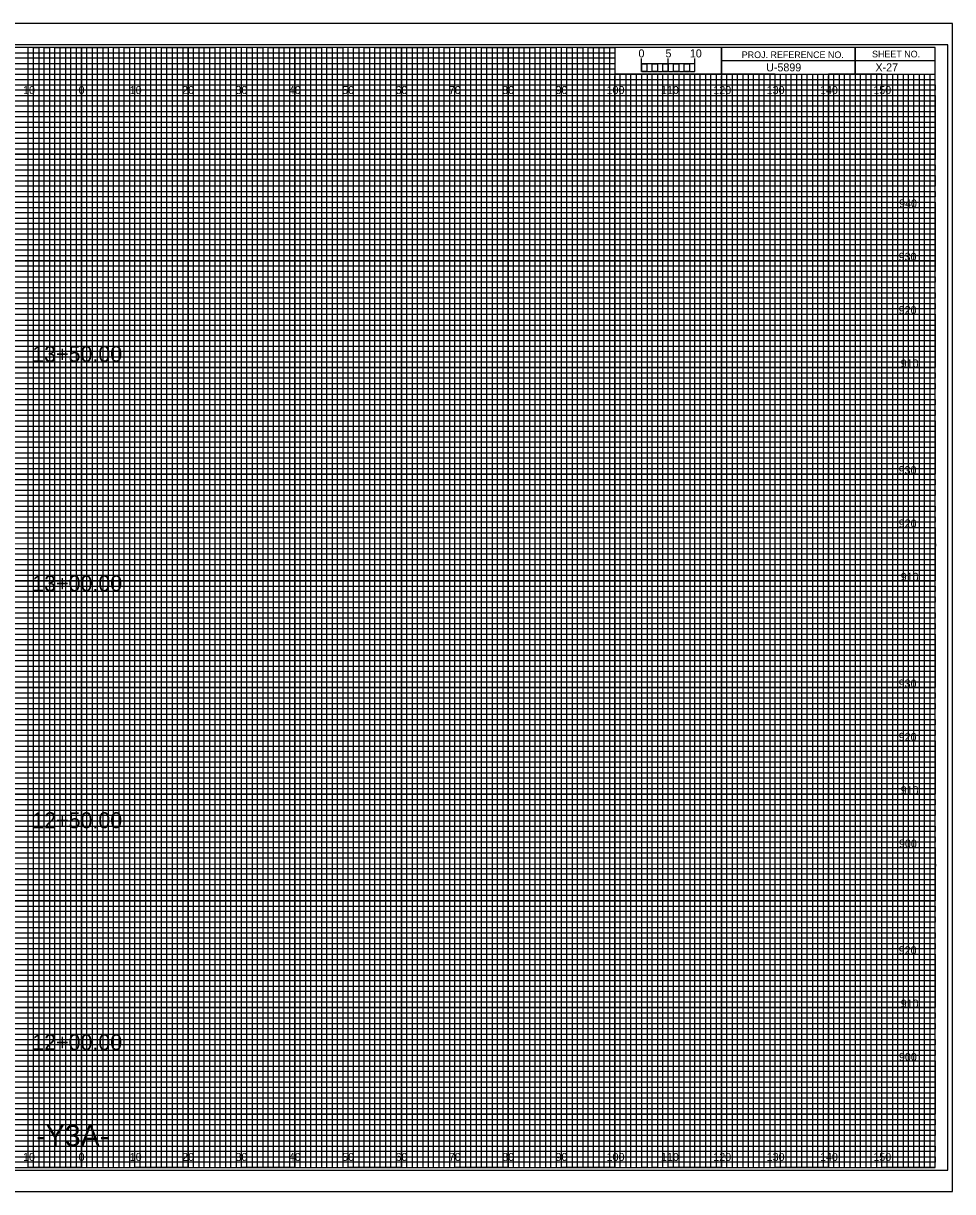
# Model space of a CAD drawing. Extents: x -13 to 323, y 216 to 434.
# Drawn here: x 149.1 to 323.3, y 215.5 to 434.5 of the extents above; entities that cross this region are included whole.
import ezdxf

# ---------------------------------------------------------------- set-up
doc = ezdxf.new("R2010")
doc.units = 0
for name, color, linetype in [('Prop XS Alignment Label', 7, 'Continuous'), ('Prop XS Bar Scale Labels', 7, 'Continuous'), ('Prop XS Elevation Labels', 7, 'Continuous'), ('Prop XS Label Text', 7, 'Continuous'), ('Prop XS Project Number', 7, 'Continuous'), ('Prop XS Sheet Number', 7, 'Continuous'), ('Prop XS Station Labels', 7, 'Continuous'), ('Scratch_Level_1', 7, 'Continuous'), ('Scratch_Level_4', 7, 'Continuous'), ('Sheet Cross Section CELL', 7, 'Continuous'), ('Sheet Cross Section Grid Minor 1 CELL', 7, 'Continuous'), ('Sheet Cross Section Grid Minor 2 CELL', 7, 'Continuous'), ('Sheet Cross Section Scale CELL', 7, 'Continuous'), ('Sheet Cutting Line CELL', 7, 'Continuous'), ('Sheet DOT Grid CELL', 7, 'Continuous'), ('Sheet Plot Border Inside CELL', 7, 'Continuous'), ('Sheet Plot Border Outside CELL', 7, 'Continuous')]:
    doc.layers.add(name, color=color, linetype=linetype)

msp = doc.modelspace()

# ---------------------------------------------------------------- linework, layer by layer
at = {"layer": 'Prop XS Label Text'}
for points in [[(145, 220), (155, 220), (155, 430), (165, 430), (165, 220), (175, 220), (175, 430), (185, 430), (185, 220), (195, 220), (195, 430), (205, 430), (205, 220), (215, 220), (215, 430), (225, 430), (225, 220), (235, 220), (235, 430), (245, 430), (245, 220), (255, 220), (255, 430), (259.93, 430), (260, 430), (260, 425), (264.99, 425), (264.99, 220), (275, 220), (275, 425), (285, 425), (285, 220), (295, 220), (295, 425), (305, 425), (305, 220), (315, 220), (315, 425)], [(0, 425), (275, 425)], [(0, 405), (320, 405), (320, 415), (0, 415)], [(0, 385), (320, 385), (320, 395), (0, 395)], [(0, 365), (320, 365), (320, 375), (0, 375)], [(0, 345), (320, 345), (320, 355), (0, 355)], [(0, 325), (320, 325), (320, 335), (0, 335)], [(0, 305), (320, 305), (320, 315), (0, 315)], [(0, 285), (320, 285), (320, 295), (0, 295)], [(0, 265), (320, 265), (320, 275), (0, 275)], [(0, 245), (320, 245), (320, 255), (0, 255)], [(0, 225), (320, 225), (320, 235), (0, 235)]]:
    msp.add_lwpolyline(points, dxfattribs=at)
at = {"layer": 'Scratch_Level_4'}
for p, q in [((150, 430), (140, 430)), ((150, 220), (150, 430)), ((170, 430), (160, 430)), ((160, 430), (160, 220)), ((170, 220), (170, 430)), ((190, 430), (180, 430)), ((180, 430), (180, 220)), ((190, 220), (190, 430)), ((210, 430), (200, 430)), ((200, 430), (200, 220)), ((210, 220), (210, 430)), ((230, 430), (220, 430)), ((220, 430), (220, 220)), ((230, 220), (230, 430)), ((250, 430), (240, 430)), ((240, 430), (240, 220)), ((250, 220), (250, 430)), ((260, 430), (260, 220)), ((270, 220), (270, 425)), ((290, 425), (280, 425)), ((280, 425), (280, 220)), ((290, 220), (290, 425)), ((310, 425), (300, 425)), ((300, 425), (300, 220)), ((310, 220), (310, 425)), ((160, 220), (150, 220)), ((180, 220), (170, 220)), ((200, 220), (190, 220)), ((220, 220), (210, 220)), ((240, 220), (230, 220)), ((260, 220), (250, 220)), ((280, 220), (270, 220)), ((300, 220), (290, 220)), ((320, 220), (310, 220)), ((320, 220), (320, 220))]:
    msp.add_line(p, q, dxfattribs=at)
for points in [[(0, 420), (320, 420), (320, 410), (0, 410)], [(0, 400), (320, 400), (320, 390), (0, 390)], [(0, 380), (320, 380), (320, 370), (0, 370)], [(0, 360), (320, 360), (320, 350), (0, 350)], [(0, 340), (320, 340), (320, 330), (0, 330)], [(0, 320), (320, 320), (320, 310), (0, 310)], [(0, 300), (320, 300), (320, 290), (0, 290)], [(0, 280), (320, 280), (320, 270), (0, 270)], [(0, 260), (320, 260), (320, 250), (0, 250)], [(0, 240), (320, 240), (320, 230), (0, 230)]]:
    msp.add_lwpolyline(points, dxfattribs=at)
at = {"layer": 'Sheet Cross Section CELL'}
for p, q in [((305, 430), (305, 425)), ((305, 425), (305, 430)), ((280, 427.5), (280, 425)), ((320, 427.49), (280, 427.49)), ((280, 425), (320, 425))]:
    msp.add_line(p, q, dxfattribs=at)
for points in [[(320, 430), (0, 430), (0, 220), (320, 220)], [(280, 430), (260, 430), (260, 425.03), (280, 425.03)], [(320, 430), (280, 430), (280, 425), (320, 425)]]:
    msp.add_lwpolyline(points, close=True, dxfattribs=at)
at = {"layer": 'Sheet Cross Section Grid Minor 1 CELL'}
for p, q in [((0, 429), (260, 429)), ((260, 427.98), (0, 427.98)), ((260, 429), (260, 427.98)), ((0, 427), (260, 427)), ((260, 425.89), (0, 425.89)), ((260, 427), (260, 425.89)), ((0, 424), (320, 424))]:
    msp.add_line(p, q, dxfattribs=at)
for points in [[(0, 423), (270, 423), (320, 423), (320, 422), (0, 422)], [(0, 421), (320, 421), (320, 419), (0, 419)], [(0, 418), (320, 418), (320, 417), (0, 416.98)], [(0, 416), (320, 416), (320, 414), (0, 414)], [(0, 413), (320, 413), (320, 412), (0, 412)], [(0, 411), (320, 411), (320, 409), (0, 409)], [(0, 408), (320, 408), (320, 407), (0, 407)], [(0, 406), (320, 406), (320, 404), (0, 404)], [(0, 403), (320, 403), (320, 402), (0, 402)], [(0, 401), (320, 401), (320, 399), (0, 399)], [(0, 398), (320, 398), (320, 397), (0, 397)], [(0, 396), (320, 396), (320, 393.95), (320, 393), (320, 392), (0, 392)], [(0, 394), (320, 394), (320, 393), (0, 393)], [(0, 391), (320, 391), (320, 389), (0, 389.03)], [(0, 389.03), (320, 389), (320, 388), (0, 388)], [(0, 387), (320, 387), (320, 386), (0, 386)], [(0, 384), (320, 384), (320, 383), (0, 383)], [(0, 382), (320, 382), (320, 381), (0, 381)], [(-0.07, 378.89), (320, 378.89), (320, 377.88), (-0.07, 377.88)], [(0, 377), (320, 377), (320, 376), (0, 376)], [(0, 374), (320, 374), (320, 373), (0, 373)], [(0, 372), (320, 372), (320, 371), (0, 371)], [(0, 369), (320, 369), (320, 368), (0, 368)], [(0, 367), (320, 367), (320, 366), (0, 366)], [(0, 364), (320, 364), (320, 363), (0, 363)], [(0, 362), (320, 362), (320, 361), (0, 361)], [(0, 359), (320, 359), (319.99, 357.98), (0, 358)], [(0, 357), (320, 357), (320, 356), (0, 356)], [(0, 354), (320, 354), (320, 353), (0, 353)], [(0, 352), (320, 352), (320, 351), (0, 351)], [(0, 349), (320, 349), (320, 348), (0, 348)], [(0, 347), (320, 347), (320, 346), (0, 346)], [(0, 344), (320, 344), (320, 343), (0, 343)], [(0, 342), (320, 342), (320, 341), (0, 341)], [(0, 339), (320, 339), (320, 338), (0, 338)], [(0, 336.99), (320.07, 336.91), (320, 336), (0, 336)], [(0, 334), (320, 334), (320, 333), (0, 333)], [(0, 332), (320, 332), (320, 331), (0, 331)], [(0, 329), (320, 329), (320, 328), (0, 328)], [(0, 327), (320, 327), (320, 326), (0, 326)], [(0, 324), (320, 324), (320, 323), (0, 323)], [(0, 322), (320, 322), (320, 321), (0, 321)], [(0, 319), (320, 319), (320, 318), (0, 318)], [(0, 317), (320, 317), (320, 316), (0, 316)], [(0, 314), (320, 314), (320, 313), (0, 313)], [(0, 312), (320, 312), (320, 311), (0, 311)], [(0, 309), (320, 309), (320, 308), (0, 308)], [(0, 307), (320, 307), (320, 306), (0, 306)], [(0, 304), (320, 304), (320, 303), (0, 303)], [(0, 302), (320, 302), (320, 301), (0, 301)], [(0, 299), (320, 299), (319.99, 297.98), (0, 298)], [(0, 297), (320, 297), (320, 296), (0, 296)], [(0, 294), (320, 294), (320, 293), (0, 293)], [(0, 292), (320, 292), (320, 291), (0, 291)], [(0, 289), (320, 289), (320, 288), (0, 288)], [(0, 287), (320, 287), (320, 286), (0, 286)], [(0, 284), (320, 284), (320, 283), (0, 283)], [(0, 282), (320, 282), (320, 281), (0, 281)], [(0, 279), (320, 279), (320, 278), (0, 278)], [(0, 276.99), (320.07, 276.91), (320, 276), (0, 276)], [(0, 274), (320, 274), (320, 273), (0, 273)], [(0, 272), (320, 272), (320, 271), (0, 271)], [(0, 269), (320, 269), (320, 268), (0, 268)], [(0, 267), (320, 267), (320, 266), (0, 266)], [(0, 264), (320, 264), (320, 263), (0, 263)], [(0, 262), (320, 262), (320, 261), (0, 261)], [(0, 259), (320, 259), (320, 258), (0, 258)], [(0, 257), (320, 257), (320, 256), (0, 256)], [(0, 254), (320, 254), (320, 253), (0, 253)], [(0, 252), (320, 252), (320, 251), (0, 251)], [(0, 249), (320, 249), (320, 248), (0, 248)], [(0, 247), (320, 247), (320, 246), (0, 246)], [(0, 244), (320, 244), (320, 243), (0, 243)], [(0, 242), (320, 242), (320, 241), (0, 241)], [(0, 239), (320, 239), (320, 238), (0, 238)], [(0, 237), (320, 237), (320, 236), (0, 236)], [(0, 234), (320, 234), (320, 233), (0, 233)], [(0, 232), (320, 232), (320, 231), (0, 231)], [(0, 229), (320, 229), (320, 228), (0, 228)], [(0, 227), (320, 227), (320, 226), (0, 226)], [(0, 224), (320, 224), (320, 223), (0, 223)], [(0, 222), (320, 222), (320, 221), (0, 221)]]:
    msp.add_lwpolyline(points, dxfattribs=at)
at = {"layer": 'Sheet Cross Section Grid Minor 2 CELL'}
for p, q in [((267, 425), (266.01, 425)), ((266.01, 425), (266.01, 220)), ((267, 220), (267, 425)), ((269, 425), (268, 425)), ((268, 425), (268, 220)), ((269, 220), (269, 425)), ((266.01, 220), (265, 220)), ((268, 220), (267, 220))]:
    msp.add_line(p, q, dxfattribs=at)
for points in [[(150, 220), (151, 220), (151, 430), (152, 430), (152, 220)], [(152, 220), (153, 220), (153, 430), (154, 430), (154, 220)], [(155, 220), (156, 220), (156, 430), (157, 430), (157, 220)], [(157, 220), (158, 220), (158, 430), (159, 430), (159, 220)], [(160, 220), (161, 220), (161, 430), (162, 430), (162, 220)], [(162, 220), (163, 220), (163, 430), (164, 430), (164, 220)], [(165, 220), (166, 220), (166, 430), (167, 430), (167, 220)], [(167, 220), (168, 220), (168, 430), (169, 430), (169, 220)], [(170, 220), (171, 220), (171, 430), (172, 430), (172, 220)], [(172, 220), (173, 220), (173, 430), (174, 430), (174, 220)], [(175, 220), (176, 220), (176, 430), (177, 430), (177, 220)], [(177, 220), (178, 220), (178, 430), (179, 430), (179, 220)], [(180, 220), (181, 220), (181, 430), (182, 430), (182, 220)], [(182, 220), (183, 220), (183, 430), (184, 430), (184, 220)], [(185, 220), (186, 220), (186, 430), (187, 430), (187, 220)], [(187, 220), (188, 220), (188, 430), (189, 430), (189, 220)], [(190, 220), (191, 220), (191, 430), (192, 430), (192, 220)], [(192, 220), (193, 220), (193, 430), (194, 430), (194, 220)], [(195, 220), (196, 220), (196, 430), (197, 430), (197, 220)], [(197, 220), (198, 220), (198, 430), (199, 430), (199, 220)], [(200, 220), (201, 220), (201, 430), (202, 430), (202, 220)], [(202, 220), (203, 220), (203, 430), (204, 430), (204, 220)], [(205, 220), (206, 220), (206, 430), (207, 430), (207, 220)], [(207, 220), (208, 220), (208, 430), (209, 430), (209, 220)], [(210, 220), (211, 220), (211, 430), (212, 430), (212, 220)], [(212, 220), (213, 220), (213, 430), (214, 430), (214, 220)], [(215, 220), (216, 220), (216, 430), (217, 430), (217, 220)], [(217, 220), (218, 220), (218, 430), (219, 430), (219, 220)], [(220, 220), (221, 220), (221, 430), (222, 430), (222, 220)], [(222, 220), (223, 220), (223, 430), (224, 430), (224, 220)], [(225, 220), (226, 220), (226, 430), (227, 430), (227, 220)], [(227, 220), (228, 220), (228, 430), (229, 430), (229, 220)], [(230, 220), (231, 220), (231, 430), (232, 430), (232, 220)], [(232, 220), (233, 220), (233, 430), (234, 430), (234, 220)], [(235, 220), (236, 220), (236, 430), (237, 430), (237, 220)], [(237, 220), (238, 220), (238, 430), (239, 430), (239, 220)], [(240, 220), (241, 220), (241, 430), (242, 430), (242, 220)], [(242, 220), (243, 220), (243, 430), (244, 430), (244, 220)], [(245, 220), (246, 220), (246, 430), (247, 430), (247, 220)], [(247, 220), (248, 220), (248, 430), (249, 430), (249, 220)], [(250, 220), (251, 220), (251, 430), (252, 430), (252, 220)], [(252, 220), (253, 220), (253, 430), (254, 430), (254, 220)], [(255, 220), (256, 220), (256, 430), (257, 430), (257, 220)], [(257, 220), (258, 220), (258, 430), (259, 430), (259, 220)], [(260, 220), (261, 220), (261, 425), (262.02, 425), (262.02, 220)], [(262, 220), (263, 220), (263, 425), (263.99, 425), (263.99, 220)], [(270, 220), (270.98, 220), (270.98, 425), (272, 425), (272, 220)], [(272, 220), (273, 220), (273, 425), (274.05, 425), (274.05, 220)], [(275, 220), (276, 220), (276, 425), (277, 425), (277, 220)], [(277, 220), (278, 220), (278, 425), (279, 425), (279, 220)], [(280, 220), (281, 220), (281, 425), (282, 425), (282, 220)], [(282, 220), (283, 220), (283, 425), (284, 425), (284, 220)], [(285, 220), (286, 220), (286, 425), (287, 425), (287, 220)], [(287, 220), (288, 220), (288, 425), (289, 425), (289, 220)], [(290, 220), (291, 220), (291, 425), (292, 425), (292, 220)], [(292, 220), (293, 220), (293, 425), (294, 425), (294, 220)], [(295, 220), (296, 220), (296, 425), (297, 425), (297, 220)], [(297, 220), (298, 220), (298, 425), (299, 425), (299, 220)], [(300, 220), (301, 220), (301, 425), (302, 425), (302, 220)], [(302, 220), (303, 220), (303, 425), (304, 425), (304, 220)], [(305, 220), (306, 220), (306, 425), (307, 425), (307, 220)], [(307, 220), (308, 220), (308, 425), (309, 425), (309, 220)], [(310, 220), (311, 220), (311, 425), (312, 425), (312, 220)], [(312, 220), (313, 220), (313, 425), (314, 425), (314, 220)], [(315, 220), (316, 220), (316, 425), (317, 425), (317, 220)], [(317, 220), (318, 220), (318, 425), (319, 425), (319, 220)]]:
    msp.add_lwpolyline(points, dxfattribs=at)
at = {"layer": 'Sheet Cross Section Scale CELL'}
for p, q in [((265, 425.49), (265, 427.9)), ((265, 426.9), (265, 427.9)), ((270, 425.49), (270, 427.9)), ((275, 425.49), (275, 427.9)), ((275, 426.9), (275, 427.9))]:
    msp.add_line(p, q, dxfattribs=at)
for points in [[(275, 426.9), (265, 426.9), (265, 425.49), (275, 425.49)], [(265, 426.9), (266, 426.9), (266, 425.49), (265, 425.49)], [(267, 426.9), (268, 426.9), (268, 425.49), (267, 425.49)], [(269, 426.9), (270, 426.9), (270, 425.49), (269, 425.49)], [(271, 426.9), (272, 426.9), (272, 425.49), (271, 425.49)], [(273, 426.9), (274, 426.9), (274, 425.49), (273, 425.49)]]:
    msp.add_lwpolyline(points, close=True, dxfattribs=at)
at = {"layer": 'Sheet Cutting Line CELL'}
for p, q in [((323.3, 434.5), (-13.4, 434.5)), ((-13.4, 215.5), (323.3, 215.5))]:
    msp.add_line(p, q, dxfattribs=at)
at = {"layer": 'Sheet DOT Grid CELL'}
for p, q in [((150, 220), (150, 430)), ((160, 220), (160, 430)), ((170, 220), (170, 430)), ((180, 220), (180, 430)), ((190, 220), (190, 430)), ((200, 220), (200, 430)), ((210, 220), (210, 430)), ((220, 220), (220, 430)), ((230, 220), (230, 430)), ((240, 220), (240, 430)), ((250, 220), (250, 430)), ((260, 220), (260, 424.69)), ((270, 220), (270, 424.69)), ((280, 220), (280, 424.69)), ((290, 220), (290, 424.69)), ((300, 220), (300, 424.69)), ((310, 220), (310, 424.69)), ((0, 420), (320, 420)), ((0, 410), (320, 410)), ((0, 400), (320, 400)), ((0, 390), (320, 390)), ((0, 380), (320, 380)), ((0, 370), (320, 370)), ((0, 360), (320, 360)), ((0, 350), (320, 350)), ((0, 340), (320, 340)), ((0, 330), (320, 330)), ((0, 320), (320, 320)), ((0, 310), (320, 310)), ((0, 300), (320, 300)), ((0, 290), (320, 290)), ((0, 280), (320, 280)), ((0, 270), (320, 270)), ((0, 260), (320, 260)), ((0, 250), (320, 250)), ((0, 240), (320, 240)), ((0, 230), (320, 230))]:
    msp.add_line(p, q, dxfattribs=at)
at = {"layer": 'Sheet Plot Border Inside CELL'}
msp.add_lwpolyline([(-10.8, 219.5), (322.4, 219.5), (322.4, 430.5), (-10.8, 430.5)], close=True, dxfattribs=at)
at = {"layer": 'Sheet Plot Border Outside CELL'}
msp.add_lwpolyline([(-13.4, 215.5), (323.3, 215.5), (323.3, 434.5), (-13.4, 434.5)], close=True, dxfattribs=at)

# ---------------------------------------------------------------- texts
at = {"layer": 'Prop XS Alignment Label'}
msp.add_text('-Y3A-', height=4, dxfattribs=at).set_placement((151.51, 224))
at = {"layer": 'Prop XS Bar Scale Labels'}
for s, p in [('5', (269.47, 428.12)), ('10', (274.04, 428.12))]:
    msp.add_text(s, height=1.5, dxfattribs=at).set_placement(p)
at = {"layer": 'Prop XS Elevation Labels'}
for s, p in [('940', (313.26, 400)), ('930', (313.18, 390)), ('920', (313.19, 380)), ('910', (313.57, 370)), ('930', (313.18, 350)), ('920', (313.19, 340)), ('910', (313.57, 330)), ('930', (313.18, 310)), ('920', (313.19, 300)), ('910', (313.57, 290)), ('900', (313.24, 280)), ('920', (313.19, 260)), ('910', (313.57, 250)), ('900', (313.24, 240))]:
    msp.add_text(s, height=1.5, dxfattribs=at).set_placement(p)
at = {"layer": 'Prop XS Project Number'}
msp.add_text('U-5899', height=1.5, dxfattribs=at).set_placement((288.34, 425.5))
at = {"layer": 'Prop XS Sheet Number'}
msp.add_text('X-27', height=1.5, dxfattribs=at).set_placement((308.83, 425.5))
at = {"layer": 'Prop XS Station Labels'}
for s, p in [('13+50.00', (150.77, 371.03)), ('13+00.00', (150.77, 328.03)), ('12+50.00', (150.77, 283.62)), ('12+00.00', (150.77, 242.01))]:
    msp.add_text(s, height=3, dxfattribs=at).set_placement(p)
at = {"layer": 'Scratch_Level_1'}
for s, p in [('10', (149.04, 421.25)), ('0', (159.45, 421.25)), ('0', (159.45, 421.25)), ('10', (169.04, 421.25)), ('20', (178.86, 421.25)), ('30', (188.86, 421.25)), ('40', (198.86, 421.25)), ('50', (208.86, 421.25)), ('60', (218.86, 421.25)), ('70', (228.86, 421.25)), ('80', (238.86, 421.25)), ('90', (248.86, 421.25)), ('100', (258.44, 421.25)), ('110', (268.62, 421.25)), ('120', (278.44, 421.25)), ('130', (288.44, 421.25)), ('140', (298.44, 421.25)), ('150', (308.44, 421.25)), ('10', (149.04, 221.25)), ('0', (159.45, 221.25)), ('0', (159.45, 221.25)), ('10', (169.04, 221.25)), ('20', (178.86, 221.25)), ('30', (188.86, 221.25)), ('40', (198.86, 221.25)), ('50', (208.86, 221.25)), ('60', (218.86, 221.25)), ('70', (228.86, 221.25)), ('80', (238.86, 221.25)), ('90', (248.86, 221.25)), ('100', (258.44, 221.25)), ('110', (268.62, 221.25)), ('120', (278.44, 221.25)), ('130', (288.44, 221.25)), ('140', (298.44, 221.25)), ('150', (308.44, 221.25))]:
    msp.add_text(s, height=1.5, dxfattribs=at).set_placement(p)
at = {"layer": 'Sheet Cross Section CELL'}
for s, p in [('PROJ. REFERENCE NO.', (283.77, 427.99)), ('SHEET NO.', (308.19, 428.12))]:
    msp.add_text(s, height=1.25, dxfattribs=at).set_placement(p)
at = {"layer": 'Sheet Cross Section Scale CELL'}
msp.add_text('0', height=1.5, dxfattribs=at).set_placement((264.41, 428.12))

doc.saveas('drawing.dxf')
